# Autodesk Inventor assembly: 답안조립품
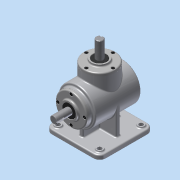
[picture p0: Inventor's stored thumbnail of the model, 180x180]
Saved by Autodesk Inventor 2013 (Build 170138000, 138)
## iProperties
Created: 2015-07
Part Number: 답안조립품
Document SubType Name: Assembly
Designer: dgall
Author: dgall
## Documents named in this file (14)
- C:\Users\dgall\Desktop\450705V1003\답안조립품.iam
- C:\Users\dgall\Desktop\450705V1003\본체.ipt
- C:\Users\dgall\Desktop\450705V1003\메인 축.ipt
- 메인 축.ipt
- C:\Users\dgall\Desktop\450705V1003\베어링 6203.ipt
- C:\Users\dgall\Desktop\450705V1003\커버.ipt
- C:\Users\dgall\Desktop\450705V1003\서브 축.ipt
- 서브 축.ipt
- C:\Users\dgall\Desktop\450705V1003\키 4x4.ipt
- C:\Users\dgall\Desktop\450705V1003\키 5x5.ipt
- C:\Users\dgall\Desktop\450705V1003\메인 베벨기어.ipt
- C:\Users\dgall\Desktop\450705V1003\서브 베벨기어.ipt
- C:\Users\dgall\Desktop\450705V1003\오일실.ipt
- C:\Users\dgall\Desktop\450705V1003\M4.ipt
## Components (8 placed, 1 different names)
1. M4:2
2. M4:3
3. M4:4
4. M4:5
5. M4:1
6. M4:6
7. M4:7
8. M4:8
